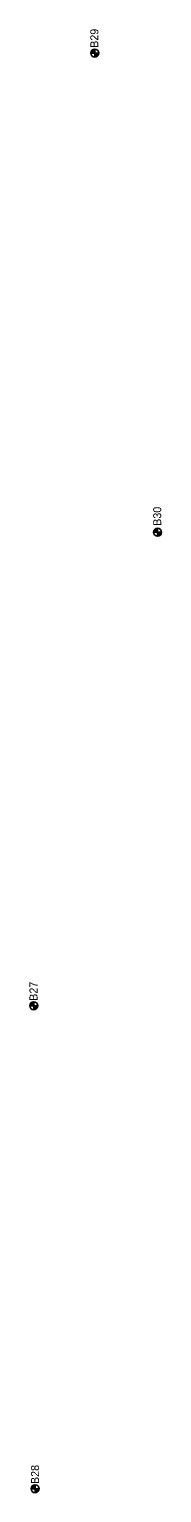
# Model space of a CAD drawing. Extents: x 327762 to 372792, y 127949 to 259367.
# Drawn here: x 361861 to 362026, y 143316 to 145145 of the extents above; entities that cross this region are included whole.
import ezdxf

# ---------------------------------------------------------------- set-up
doc = ezdxf.new("R2010")
doc.units = 0
for name, color, linetype in [('E_SOIL_BORE1 [KAPUR_CADDS_LEVELS]', 7, 'Continuous'), ('E_SOIL_BORE2 [KAPUR_CADDS_LEVELS]', 7, 'Continuous'), ('P_MARK', 7, 'Continuous')]:
    doc.layers.add(name, color=color, linetype=linetype)

msp = doc.modelspace()

# ---------------------------------------------------------------- linework, layer by layer
at = {"layer": 'P_MARK'}
for p, q in [((361942.3, 145120.6), (361942.3, 145110.6)), ((361937.3, 145115.6), (361947.3, 145115.6)), ((362015.7, 144516.7), (362025.7, 144516.7)), ((362020.7, 144521.7), (362020.7, 144511.7)), ((361861.3, 143924.9), (361871.3, 143924.9)), ((361866.3, 143929.9), (361866.3, 143919.9)), ((361863, 143321.3), (361873, 143321.3)), ((361868, 143326.3), (361868, 143316.3))]:
    msp.add_line(p, q, dxfattribs=at)
for centre in [(361942.3, 145115.6), (362020.7, 144516.7), (361866.3, 143924.9), (361868, 143321.3)]:
    msp.add_circle(centre, 5, dxfattribs=at)
for centre, radius, start, end in [((361942.3, 145115.6), 4.5, 89.9869, 179.9869), ((361942.3, 145115.6), 4, 89.9869, 179.9869), ((361942.3, 145115.6), 3.5, 89.9869, 179.9869), ((361942.3, 145115.6), 3, 89.9869, 179.9869), ((361942.3, 145115.6), 2.5, 89.9869, 179.9869), ((361942.3, 145115.6), 2, 89.9869, 179.9869), ((361942.3, 145115.6), 1.5, 89.9869, 179.9869), ((361942.3, 145115.6), 1, 89.9869, 179.9869), ((361942.3, 145115.6), 0.5, 89.9869, 179.9869), ((361942.3, 145115.6), 4.5, 269.9869, 359.9869), ((361942.3, 145115.6), 4, 269.9869, 359.9869), ((361942.3, 145115.6), 3.5, 269.9869, 359.9869), ((361942.3, 145115.6), 3, 269.9869, 359.9869), ((361942.3, 145115.6), 2.5, 269.9869, 359.9869), ((361942.3, 145115.6), 2, 269.9869, 359.9869), ((361942.3, 145115.6), 1.5, 269.9869, 359.9869), ((361942.3, 145115.6), 1, 269.9869, 359.9869), ((361942.3, 145115.6), 0.5, 269.9869, 359.9869), ((362020.7, 144516.7), 4.5, 89.9869, 179.9869), ((362020.7, 144516.7), 4, 89.9869, 179.9869), ((362020.7, 144516.7), 3.5, 89.9869, 179.9869), ((362020.7, 144516.7), 3, 89.9869, 179.9869), ((362020.7, 144516.7), 2.5, 89.9869, 179.9869), ((362020.7, 144516.7), 2, 89.9869, 179.9869), ((362020.7, 144516.7), 1.5, 89.9869, 179.9869), ((362020.7, 144516.7), 1, 89.9869, 179.9869), ((362020.7, 144516.7), 0.5, 89.9869, 179.9869), ((362020.7, 144516.7), 4.5, 269.9869, 359.9869), ((362020.7, 144516.7), 4, 269.9869, 359.9869), ((362020.7, 144516.7), 3.5, 269.9869, 359.9869), ((362020.7, 144516.7), 3, 269.9869, 359.9869), ((362020.7, 144516.7), 2.5, 269.9869, 359.9869), ((362020.7, 144516.7), 2, 269.9869, 359.9869), ((362020.7, 144516.7), 1.5, 269.9869, 359.9869), ((362020.7, 144516.7), 1, 269.9869, 359.9869), ((362020.7, 144516.7), 0.5, 269.9869, 359.9869), ((361866.3, 143924.9), 4.5, 89.9869, 179.9869), ((361866.3, 143924.9), 4, 89.9869, 179.9869), ((361866.3, 143924.9), 3.5, 89.9869, 179.9869), ((361866.3, 143924.9), 3, 89.9869, 179.9869), ((361866.3, 143924.9), 2.5, 89.9869, 179.9869), ((361866.3, 143924.9), 2, 89.9869, 179.9869), ((361866.3, 143924.9), 1.5, 89.9869, 179.9869), ((361866.3, 143924.9), 1, 89.9869, 179.9869), ((361866.3, 143924.9), 0.5, 89.9869, 179.9869), ((361866.3, 143924.9), 4.5, 269.9869, 359.9869), ((361866.3, 143924.9), 4, 269.9869, 359.9869), ((361866.3, 143924.9), 3.5, 269.9869, 359.9869), ((361866.3, 143924.9), 3, 269.9869, 359.9869), ((361866.3, 143924.9), 2.5, 269.9869, 359.9869), ((361866.3, 143924.9), 2, 269.9869, 359.9869), ((361866.3, 143924.9), 1.5, 269.9869, 359.9869), ((361866.3, 143924.9), 1, 269.9869, 359.9869), ((361866.3, 143924.9), 0.5, 269.9869, 359.9869), ((361868, 143321.3), 4.5, 89.9869, 179.9869), ((361868, 143321.3), 4, 89.9869, 179.9869), ((361868, 143321.3), 3.5, 89.9869, 179.9869), ((361868, 143321.3), 3, 89.9869, 179.9869), ((361868, 143321.3), 2.5, 89.9869, 179.9869), ((361868, 143321.3), 2, 89.9869, 179.9869), ((361868, 143321.3), 1.5, 89.9869, 179.9869), ((361868, 143321.3), 1, 89.9869, 179.9869), ((361868, 143321.3), 0.5, 89.9869, 179.9869), ((361868, 143321.3), 4.5, 269.9869, 359.9869), ((361868, 143321.3), 4, 269.9869, 359.9869), ((361868, 143321.3), 3.5, 269.9869, 359.9869), ((361868, 143321.3), 3, 269.9869, 359.9869), ((361868, 143321.3), 2.5, 269.9869, 359.9869), ((361868, 143321.3), 2, 269.9869, 359.9869), ((361868, 143321.3), 1.5, 269.9869, 359.9869), ((361868, 143321.3), 1, 269.9869, 359.9869), ((361868, 143321.3), 0.5, 269.9869, 359.9869)]:
    msp.add_arc(centre, radius, start, end, dxfattribs=at)

# ---------------------------------------------------------------- texts
at = {"layer": 'E_SOIL_BORE1 [KAPUR_CADDS_LEVELS]'}
for s, p in [('B30', (362025.2, 144524.8)), ('B27', (361871, 143931.2))]:
    msp.add_text(s, height=10, rotation=89.9869, dxfattribs=at).set_placement(p)
at = {"layer": 'E_SOIL_BORE2 [KAPUR_CADDS_LEVELS]'}
for s, p in [('B29', (361946.8, 145122.2)), ('B28', (361872.9, 143327.2))]:
    msp.add_text(s, height=10, rotation=89.9869, dxfattribs=at).set_placement(p)

doc.saveas('drawing.dxf')
